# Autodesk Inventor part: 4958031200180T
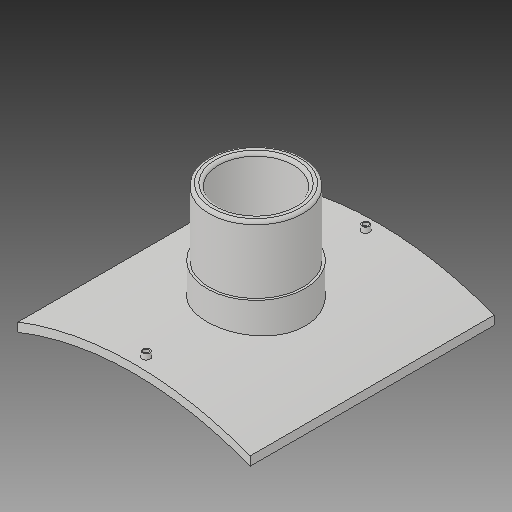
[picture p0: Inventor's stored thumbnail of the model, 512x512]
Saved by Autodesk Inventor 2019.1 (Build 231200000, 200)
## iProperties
Created: 2017-10
Part Number: 4958031200180T
Material: Generic
Description: PLASSON BRANCH SADDLE 1200x180
Document SubType Name: Modeling
Designer: KIM
Mass: 2754.05 g
Surface Area: 3037.44 cm^2
Volume: 2754.05 cm^3
Density: 1 g/cm^3
Appearance: Default
Author: KIM
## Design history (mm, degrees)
derived "495803.ipt"
feature "Solid1::495803.ipt"
tag "TaggingFeature1"
body "Solid1"
other parameters: "d1" = 16, "d2" = 447, "d4" = 0, "d12" = 625.6, "d13" = 14, "d14" = 211.5, "d16" = 5 deg, "d18" = 4, "d19" = 14, "d20" = 0, "d21" = 3, "d22" = 0, "d24" = 189, "d25" = 16, "d26" = 144, "d28" = 0, "d29" = 9.6, "d31" = 0, "d32" = 92, "d33" = 0, "d34" = 12, "d37" = 128.8, "d38" = 0, "d39" = 6, "B_" = 447, "H_" = 184, "x_" = 16, "D_" = 16
